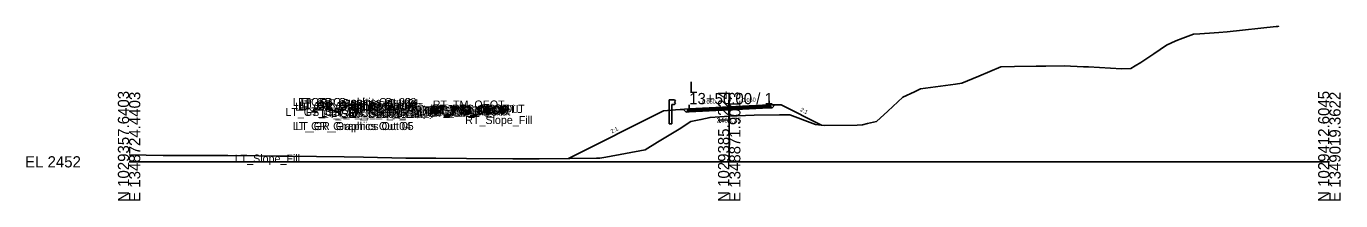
# Model space of a CAD drawing. Extents: x -26 to 1453, y -10 to 4527.
# Drawn here: x -25.7 to 302.8, y 3490.3 to 3533.8 of the extents above; entities that cross this region are included whole.
import ezdxf

# ---------------------------------------------------------------- set-up
doc = ezdxf.new("R2010")
doc.units = 0
for name, color, linetype in [('Default', 7, 'Continuous'), ('Exist Cross Section Cell', 7, 'Continuous'), ('Exist XS Center Line Elevation Label', 7, 'Continuous'), ('Exist XS Ground Line', 7, 'Continuous'), ('Prop CMT Guardrail Graphics', 7, 'Continuous'), ('Prop CMT Pvmt Course 1', 7, 'Continuous'), ('Prop CMT Pvmt Course 2', 7, 'Continuous'), ('Prop CMT Pvmt Course 3', 7, 'Continuous'), ('Prop CMT Pvmt Surface', 7, 'Continuous'), ('Prop CMT Pvmt Surface Overlay', 7, 'Continuous'), ('Prop CMT Pvmt Surface Shoulder', 7, 'Continuous'), ('Prop CMT Shld Paved Course 1', 7, 'Continuous'), ('Prop CMT Shld Paved Course 2', 7, 'Continuous'), ('Prop CMT Shld Paved Course 3', 7, 'Continuous'), ('Prop CMT Slope Grass', 7, 'Continuous'), ('Prop CMT Subgrade Earthwork', 7, 'Continuous'), ('Prop XS Earthwork Shape', 7, 'Continuous'), ('Prop XS EOT Tick Mark', 7, 'Continuous'), ('Prop XS SE Text', 7, 'Continuous'), ('Prop XS Side Slope Text', 7, 'Continuous')]:
    doc.layers.add(name, color=color, linetype=linetype)

msp = doc.modelspace()

# ---------------------------------------------------------------- linework, layer by layer
at = {"layer": 'Exist Cross Section Cell'}
for p, q in [((150, 3500), (150, 3517.18)), ((0, 3500), (150, 3500)), ((150, 3500), (300, 3500))]:
    msp.add_line(p, q, dxfattribs=at)
at = {"layer": 'Exist XS Ground Line'}
msp.add_lwpolyline([(0, 3501.74), (8.56, 3501.61), (11.94, 3501.59), (23.29, 3501.59), (24.72, 3501.59), (32.46, 3501.49), (37.58, 3501.43), (38.5, 3501.41), (39.92, 3501.4), (53.79, 3501.27), (58.61, 3501.18), (69.2, 3500.93), (76.66, 3500.88), (84.37, 3500.81), (95.94, 3500.77), (99.57, 3500.74), (102.48, 3500.73), (110.13, 3500.81), (116.86, 3500.92), (117.64, 3500.95), (119.19, 3501.2), (128.97, 3503.01), (132.09, 3504.88), (137.46, 3508.16), (140.39, 3510.05), (142.93, 3510.55), (145.22, 3511.08), (147.68, 3511.23), (150, 3511.35), (154.08, 3511.57), (156.22, 3511.64), (162.58, 3511.76), (165.12, 3511.75), (165.12, 3511.75), (165.14, 3511.75), (171.54, 3509.28), (173.82, 3509.1), (181.95, 3509.13), (183.33, 3509.22), (184.53, 3509.58), (186.81, 3510.09), (189.67, 3512.65), (193.42, 3516.11), (196.33, 3517.46), (197.83, 3518.23), (206.53, 3519.4), (208.17, 3519.65), (212.4, 3521.35), (217.91, 3523.71), (221.27, 3523.75), (226.73, 3523.84), (229.16, 3523.84), (233.75, 3523.91), (233.76, 3523.91), (238.52, 3523.7), (239.77, 3523.68), (248.04, 3523.23), (250.39, 3523.31), (251.5, 3523.98), (252.85, 3524.79), (256.17, 3526.93), (259.33, 3529.13), (261.62, 3530.17), (263.37, 3530.89), (266.03, 3531.87), (267.65, 3531.94), (271.2, 3532.21), (272.4, 3532.28), (274.47, 3532.41), (286.7, 3533.75), (287.04, 3533.77), (287.26, 3533.81), (287.27, 3533.8), (287.29, 3533.8)], dxfattribs=at)
at = {"layer": 'Prop CMT Guardrail Graphics'}
for points in [[(134.99, 3509.44), (134.99, 3515.44)], [(134.99, 3515.44), (136.32, 3515.44), (136.59, 3515.14)], [(136.59, 3514.56), (136.32, 3514.27), (135.66, 3514.27)], [(135.66, 3514.27), (135.66, 3509.44)], [(136.59, 3515.14), (136.32, 3514.85)], [(136.32, 3514.85), (136.59, 3514.56)], [(135.66, 3509.44), (134.99, 3509.44)]]:
    msp.add_lwpolyline(points, dxfattribs=at)
at = {"layer": 'Prop CMT Pvmt Course 1'}
for points in [[(150, 3513.71), (140, 3513.21)], [(140, 3512.96), (150, 3513.46)], [(140, 3513.21), (140, 3512.96)], [(150, 3513.71), (160, 3514.21)], [(160, 3513.96), (150, 3513.46)], [(150, 3513.58), (150, 3513.71)], [(150, 3513.58), (150, 3513.71)], [(150, 3513.46), (150, 3513.58), (150, 3513.58)], [(150, 3513.46), (150, 3513.58), (150, 3513.58)], [(160, 3514.21), (160, 3513.96)]]:
    msp.add_lwpolyline(points, dxfattribs=at)
at = {"layer": 'Prop CMT Pvmt Course 2'}
for points in [[(150, 3513.46), (140, 3512.96)], [(140, 3512.71), (150, 3513.21)], [(140, 3512.96), (140, 3512.71)], [(150, 3513.46), (160, 3513.96)], [(160, 3513.71), (150, 3513.21)], [(150, 3513.21), (150, 3513.46)], [(150, 3513.21), (150, 3513.46)], [(160, 3513.96), (160, 3513.71)]]:
    msp.add_lwpolyline(points, dxfattribs=at)
at = {"layer": 'Prop CMT Pvmt Course 3'}
for points in [[(150, 3513.21), (140, 3512.71)], [(140, 3512.46), (150, 3512.96)], [(140, 3512.71), (140, 3512.46)], [(150, 3513.21), (160, 3513.71)], [(160, 3513.46), (150, 3512.96)], [(150, 3512.96), (150, 3513.21)], [(150, 3512.96), (150, 3513.21)], [(160, 3513.71), (160, 3513.46)]]:
    msp.add_lwpolyline(points, dxfattribs=at)
at = {"layer": 'Prop CMT Pvmt Surface'}
for points in [[(150, 3513.71), (140, 3513.21)], [(150, 3513.71), (160, 3514.21)]]:
    msp.add_lwpolyline(points, dxfattribs=at)
at = {"layer": 'Prop CMT Pvmt Surface Overlay'}
for points in [[(150, 3513.71), (140, 3513.21)], [(150, 3513.71), (160, 3514.21)]]:
    msp.add_lwpolyline(points, dxfattribs=at)
at = {"layer": 'Prop CMT Pvmt Surface Shoulder'}
for points in [[(140, 3513.21), (140, 3513.21)], [(160, 3514.21), (160, 3514.21)]]:
    msp.add_lwpolyline(points, dxfattribs=at)
at = {"layer": 'Prop CMT Shld Paved Course 1'}
for points in [[(140, 3513.21), (140, 3513.21), (139.74, 3512.94)], [(139.74, 3512.94), (140, 3512.96)], [(140, 3512.96), (140, 3513.21)], [(160, 3514.21), (160, 3514.21), (160.24, 3513.97)], [(160, 3513.96), (160, 3514.21)], [(160.24, 3513.97), (160, 3513.96)]]:
    msp.add_lwpolyline(points, dxfattribs=at)
at = {"layer": 'Prop CMT Shld Paved Course 2'}
for points in [[(140, 3512.96), (139.74, 3512.94), (139.47, 3512.68)], [(139.47, 3512.68), (140, 3512.71)], [(140, 3512.71), (140, 3512.96)], [(160, 3513.96), (160.24, 3513.97), (160.48, 3513.73)], [(160, 3513.71), (160, 3513.96)], [(160.48, 3513.73), (160, 3513.71)]]:
    msp.add_lwpolyline(points, dxfattribs=at)
at = {"layer": 'Prop CMT Shld Paved Course 3'}
for points in [[(139.47, 3512.68), (139.21, 3512.42)], [(139.21, 3512.42), (140, 3512.46)], [(140, 3512.71), (139.47, 3512.68)], [(139.47, 3512.68), (139.47, 3512.68)], [(140, 3512.46), (140, 3512.71)], [(160, 3513.71), (160.48, 3513.73)], [(160, 3513.46), (160, 3513.71)], [(160.72, 3513.49), (160, 3513.46)], [(160.48, 3513.73), (160.48, 3513.73)], [(160.48, 3513.73), (160.72, 3513.49)]]:
    msp.add_lwpolyline(points, dxfattribs=at)
at = {"layer": 'Prop CMT Slope Grass'}
for points in [[(133.59, 3512.7), (109.81, 3500.8)], [(136.59, 3512.94), (133.59, 3512.7)], [(140, 3513.21), (136.59, 3512.94)], [(160, 3514.21), (163, 3514.18)], [(163, 3514.18), (173.03, 3509.16)]]:
    msp.add_lwpolyline(points, dxfattribs=at)
at = {"layer": 'Prop CMT Subgrade Earthwork'}
for points in [[(139.21, 3512.42), (138.54, 3513.09)], [(140, 3512.46), (139.21, 3512.42)], [(150, 3512.96), (140, 3512.46)], [(150, 3512.96), (160, 3513.46)], [(160, 3513.46), (160.72, 3513.49)], [(160.72, 3513.49), (161.42, 3514.19)]]:
    msp.add_lwpolyline(points, dxfattribs=at)
at = {"layer": 'Prop XS Earthwork Shape'}
msp.add_lwpolyline([(136.59, 3512.94), (133.59, 3512.7), (109.81, 3500.8), (110.13, 3500.81), (116.86, 3500.92), (117.64, 3500.95), (119.19, 3501.2), (128.97, 3503.01), (132.09, 3504.88), (137.46, 3508.16), (140.39, 3510.05), (142.93, 3510.55), (145.22, 3511.08), (147.68, 3511.23), (150, 3511.35), (154.08, 3511.57), (156.22, 3511.64), (162.58, 3511.76), (165.12, 3511.75), (165.14, 3511.75), (171.54, 3509.28), (173.03, 3509.16), (163, 3514.18), (161.42, 3514.19), (160.72, 3513.49), (160, 3513.46), (150, 3512.96), (140, 3512.46), (139.21, 3512.42), (138.54, 3513.09)], close=True, dxfattribs=at)
msp.add_lwpolyline([(136.59, 3512.94), (133.59, 3512.7), (109.81, 3500.8), (110.13, 3500.81), (116.86, 3500.92), (117.64, 3500.95), (119.19, 3501.2), (128.97, 3503.01), (132.09, 3504.88), (137.46, 3508.16), (140.39, 3510.05), (142.93, 3510.55), (145.22, 3511.08), (147.68, 3511.23), (150, 3511.35), (154.08, 3511.57), (156.22, 3511.64), (162.58, 3511.76), (165.12, 3511.75), (165.14, 3511.75), (171.54, 3509.28), (173.03, 3509.16), (163, 3514.18), (161.42, 3514.19), (160.72, 3513.49), (160, 3513.46), (150, 3512.96), (140, 3512.46), (139.21, 3512.42), (138.54, 3513.09)], close=True, dxfattribs=at)
at = {"layer": 'Prop XS EOT Tick Mark'}
for points in [[(140, 3513.21), (140, 3514.21)], [(160, 3514.21), (160, 3515.21)]]:
    msp.add_lwpolyline(points, dxfattribs=at)

# ---------------------------------------------------------------- texts
at = {"layer": 'Default'}
for s, height, p in [('LT_GR_Graphics Out 03', 2, (40.89, 3513.92)), ('LT_GR_Graphics Out 02', 2, (42.22, 3513.92)), ('LT_GR_Graphics Out 09', 2, (42.22, 3513.34)), ('LT_GR_Graphics Out 01', 2, (43.06, 3513.63)), ('RT_TM_OEOT', 2, (75.9, 3513.3)), ('LT_GS_OS_GR_Face_Graphics', 2, (39.05, 3511.42)), ('LT_GR_Graphics Out 06', 2, (41.51, 3512.76)), ('LT_GR_Graphics Out 07', 2, (42.22, 3512.76)), ('LT_GR_Graphics Out 08', 2, (42.49, 3513.05)), ('LT_Sub_Trench_Out_DLT', 2, (44.13, 3511.58)), ('LT_GS_OS_CTL', 2, (47.96, 3511.18)), ('LT_Sub_Trench_Out', 2, (48.43, 3510.92)), ('LT_PS3_Shelf_Out', 2, (50.47, 3511.18)), ('LT_PS3_OEOP', 2, (54.72, 3511.18)), ('LT_PS2_OEOP', 2, (54.98, 3511.44)), ('LT_Sub_OEOT', 2, (55.08, 3510.95)), ('LT_PV2_OEOT', 2, (55.17, 3511.45)), ('LT_PV3_OEOT', 2, (55.17, 3511.2)), ('LT_PV1_OEOT', 2, (55.74, 3511.7)), ('LT_PS1_OEOP', 2, (55.8, 3511.7)), ('LT_TM_OEOT', 2, (55.94, 3512.7)), ('RT_PV1_OEEOP_W', 2, (62.94, 3511.87)), ('LT_PV1_OEEOP_W', 2, (62.98, 3511.87)), ('RT_Sub_OEEOP', 2, (64.17, 3511.25)), ('LT_Sub_OEEOP', 2, (64.21, 3511.25)), ('RT_PV2_OEEOP', 2, (64.26, 3511.75)), ('RT_PV3_OEEOP', 2, (64.26, 3511.5)), ('LT_PV2_OEEOP', 2, (64.31, 3511.75)), ('LT_PV3_OEEOP', 2, (64.31, 3511.5)), ('RT_Sub_Trench_Out_DLT', 2, (66.93, 3512.25)), ('PV1_PGL_W', 2, (67.58, 3511.87)), ('PV1_PGL', 2, (69.47, 3512)), ('RT_Sub_Trench_Out', 2, (69.89, 3511.57)), ('RT_PS3_Shelf_Out', 2, (71.42, 3511.81)), ('RT_Sub_OEOT', 2, (75.03, 3511.55)), ('RT_PV2_OEOT', 2, (75.13, 3512.05)), ('RT_PV3_OEOT', 2, (75.13, 3511.8)), ('RT_PS2_OEOP', 2, (75.43, 3512.05)), ('RT_PS3_OEOP', 2, (75.68, 3511.81)), ('RT_PV1_OEOT', 2, (75.69, 3512.3)), ('RT_PS1_OEOP', 2, (75.76, 3512.3)), ('RT_GS_OS_CTL', 2, (77.32, 3512.21)), ('LT_GR_Graphics Out 04', 2, (40.89, 3507.92)), ('LT_GR_Graphics Out 05', 2, (41.55, 3507.92)), ('RT_Slope_Fill', 2, (84.01, 3509.44)), ('-', 0.0001, (0, 3500)), ('-', 0.0001, (0, 3500)), ('-', 0.0001, (0, 3500)), ('-', 0.0001, (0, 3500)), ('LT_Slope_Fill', 2, (26.38, 3499.82))]:
    msp.add_text(s, height=height, dxfattribs=at).set_placement(p)
at = {"layer": 'Exist Cross Section Cell'}
for s, p in [('L', (140, 3517.18)), ('13+50.00 / 1', (140, 3514.38)), ('EL 2452', (-26, 3498.6))]:
    msp.add_text(s, height=2.8, dxfattribs=at).set_placement(p)
for s, p in [('N 1029357.6403', (0, 3490)), ('E 1348724.4403', (2.8, 3490)), ('N 1029385.1224', (150, 3490)), ('E 1348871.9013', (152.8, 3490)), ('N 1029412.6045', (300, 3490)), ('E 1349019.3622', (302.8, 3490))]:
    msp.add_text(s, height=2.8, rotation=90, dxfattribs=at).set_placement(p)
at = {"layer": 'Exist XS Center Line Elevation Label'}
msp.add_text('2463.35', height=1.23, dxfattribs=at).set_placement((146.85, 3509.76))
at = {"layer": 'Prop XS SE Text'}
for p in [(143.2, 3514.37), (153.2, 3514.87)]:
    msp.add_text('0.050', height=1, rotation=2.8624, dxfattribs=at).set_placement(p)
at = {"layer": 'Prop XS Side Slope Text'}
for rotation, p in [(333.4349, (167.64, 3512.7)), (26.5651, (120.66, 3507.07))]:
    msp.add_text('2:1', height=1, rotation=rotation, dxfattribs=at).set_placement(p)

doc.saveas('drawing.dxf')
